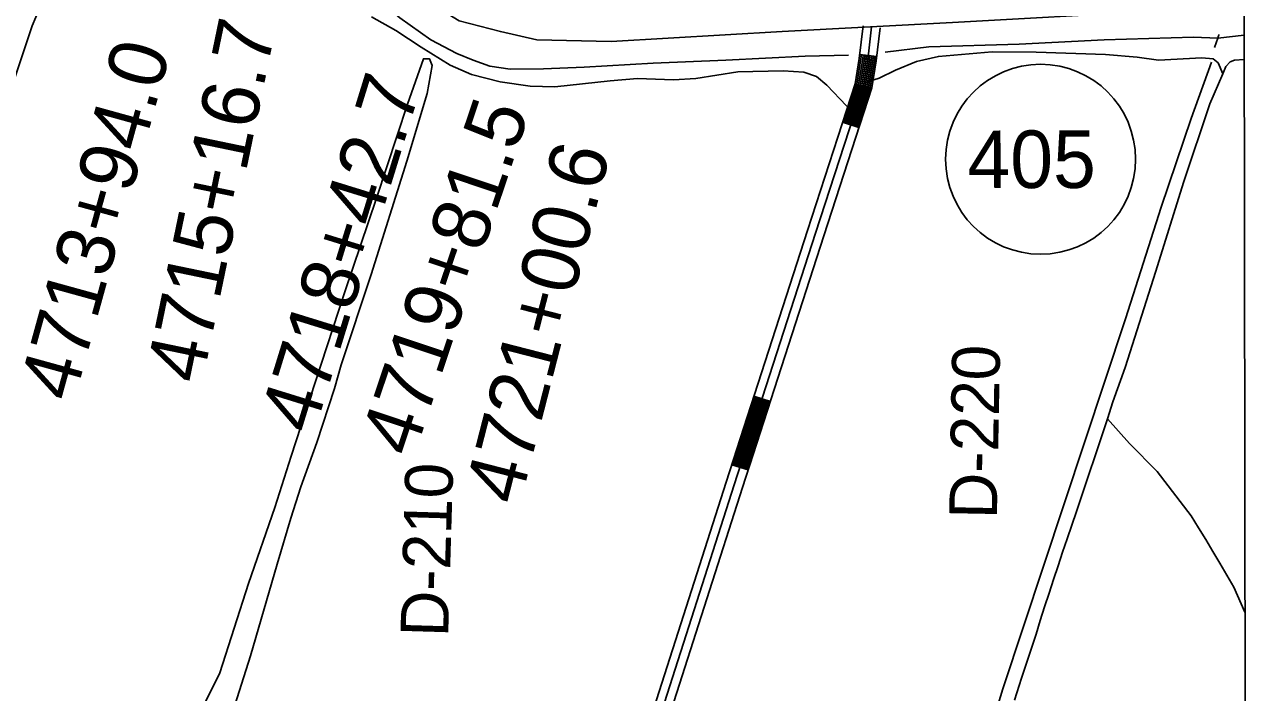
# Model space of a CAD drawing. Extents: x 3297772 to 3335630, y 634068 to 659439.
# Drawn here: x 3331326 to 3333452, y 643601 to 644761 of the extents above; entities that cross this region are included whole.
import ezdxf

# ---------------------------------------------------------------- set-up
doc = ezdxf.new("R2010")
doc.units = 0
for name, color, linetype in [('V-DTCH-CNTR', 7, 'Continuous'), ('V-GRID-FRAM', 7, 'Continuous'), ('V-RIVR-RANG-IDEN', 7, 'Continuous'), ('V-ROAD-CNTR', 7, 'Continuous'), ('V-ROAD-IDEN', 7, 'Continuous'), ('V-SITE-VEGE', 7, 'Continuous'), ('V-SURV-IDEN', 7, 'Continuous'), ('V-TOPO-SHOR', 7, 'Continuous')]:
    doc.layers.add(name, color=color, linetype=linetype)

msp = doc.modelspace()

# ---------------------------------------------------------------- linework, layer by layer
at = {"layer": 'V-DTCH-CNTR'}
msp.add_line((3333206.8, 644076.4), (3333153.2, 643915.1), dxfattribs=at)
for points in [[(3331358.2, 644804.5), (3331338.7, 644758.7), (3331279.3, 644581.4)], [(3332769.3, 644603.4), (3332753.8, 644619.7), (3332719.6, 644655.9), (3332701.7, 644670.7), (3332679.2, 644678.5), (3332643.4, 644680.5), (3332564.9, 644678.7), (3332491.7, 644667.5), (3332453.2, 644665.2), (3332390.6, 644667.2), (3332342.8, 644663.4), (3332247.1, 644653), (3332203.9, 644654.2), (3332152.2, 644661.7), (3332102.4, 644674.5), (3332065.1, 644690.5), (3332014.6, 644722.1), (3331970.7, 644750.5), (3331928.3, 644774.7)], [(3333407.2, 644675.6), (3333399.1, 644694.6), (3333390.5, 644701.6), (3333371.1, 644703.2), (3333295.6, 644699.4), (3333258.3, 644704.5), (3333203.4, 644709.2), (3333083.3, 644713.3), (3333006.7, 644713.8), (3332913.3, 644705.7), (3332875.2, 644696.8), (3332838.6, 644682.1), (3332810.2, 644668.1), (3332784, 644660.1)], [(3333444.4, 644700.4), (3333427.5, 644699.2), (3333420.1, 644696.1), (3333412.7, 644688.4), (3333407.2, 644675.6)], [(3333407.2, 644675.6), (3333384.7, 644623.5), (3333339, 644487), (3333291, 644332.6), (3333237.9, 644165.1), (3333216.4, 644105.6), (3333206.8, 644076.4)], [(3333206.8, 644076.4), (3333245.2, 644033.6), (3333293, 643984.9), (3333352.4, 643907.5)], [(3333153.2, 643915.1), (3333145, 643891.6), (3333137, 643868), (3333129, 643844.4), (3333121.1, 643820.7), (3333113.2, 643797.1), (3333105.5, 643773.4), (3333097.8, 643749.6), (3333090.3, 643725.9), (3333082.8, 643702.1), (3333070.1, 643663.9), (3333057.6, 643625.6), (3333045.3, 643587.3)], [(3333352.4, 643907.5), (3333365, 643887), (3333377.6, 643866.5), (3333389.9, 643845.9), (3333402.2, 643825.3), (3333414.2, 643804.5), (3333426.2, 643783.7), (3333445.8, 643740.2)]]:
    msp.add_lwpolyline(points, dxfattribs=at)
at = {"layer": 'V-GRID-FRAM'}
msp.add_lwpolyline([(3301870.2, 657630.6), (3333425.5, 657662.7), (3333452, 639478.7), (3301880.8, 639446.5), (3301870.2, 657630.6)], dxfattribs=at)
at = {"layer": 'V-ROAD-CNTR'}
for p, q in [((3332806.3, 644705.8), (3332776.5, 644709.2)), ((3332775.3, 644582), (3332746.7, 644591.3)), ((3332621.3, 644106.3), (3332592.8, 644115.6)), ((3332582.9, 643987.4), (3332554.3, 643996.6))]:
    msp.add_line(p, q, dxfattribs=at)
for points in [[(3331179.9, 644989.5), (3331441, 645002.9), (3331521.1, 645001.9), (3331578.7, 644990.8), (3331648, 644970.9), (3331747.7, 644939.4), (3331871.6, 644891.7), (3331950.6, 644848.9), (3332022.3, 644803.4), (3332081, 644767.4), (3332152.5, 644748.8), (3332215.7, 644734.7), (3332344.8, 644731.4), (3332641.7, 644748.8), (3332937.5, 644764.7), (3333291.4, 644784.2), (3333441.9, 644790.5)], [(3332782.3, 644758.9), (3332775.7, 644702.1), (3332768.5, 644658.2), (3332685.7, 644403.2), (3332544.4, 643966), (3332358.5, 643385.7)], [(3332797.2, 644757.1), (3332790.6, 644700), (3332783.1, 644654.7), (3332700, 644398.6), (3332558.7, 643961.4), (3332372.7, 643381.1)], [(3332812.1, 644755.4), (3332805.4, 644697.9), (3332797.7, 644651.1), (3332714.2, 644394), (3332573, 643956.8), (3332387, 643376.5)], [(3332779.5, 644708.9), (3332778.7, 644701.7), (3332771.4, 644657.5), (3332749.6, 644590.3)], [(3332782.5, 644708.5), (3332781.7, 644701.3), (3332774.3, 644656.8), (3332752.4, 644589.4)], [(3332785.5, 644708.2), (3332784.6, 644700.8), (3332777.2, 644656.1), (3332755.3, 644588.5)], [(3332788.5, 644707.8), (3332787.6, 644700.4), (3332780.2, 644655.4), (3332758.2, 644587.6)], [(3332791.4, 644707.5), (3332790.6, 644700), (3332783.1, 644654.7), (3332761, 644586.6)], [(3332794.4, 644707.1), (3332793.6, 644699.6), (3332786, 644654), (3332763.9, 644585.7)], [(3332797.4, 644706.8), (3332796.5, 644699.2), (3332788.9, 644653.2), (3332766.7, 644584.8)], [(3332800.4, 644706.4), (3332799.5, 644698.8), (3332791.9, 644652.5), (3332769.6, 644583.9)], [(3332803.4, 644706.1), (3332802.5, 644698.3), (3332794.8, 644651.8), (3332772.4, 644582.9)], [(3332595.6, 644114.6), (3332557.2, 643995.7)], [(3332598.5, 644113.7), (3332560, 643994.8)], [(3332601.3, 644112.8), (3332562.9, 643993.8)], [(3332604.2, 644111.9), (3332565.7, 643992.9)], [(3332607, 644110.9), (3332568.6, 643992)], [(3332609.9, 644110), (3332571.4, 643991.1)], [(3332612.7, 644109.1), (3332574.3, 643990.1)], [(3332615.6, 644108.2), (3332577.2, 643989.2)], [(3332618.4, 644107.2), (3332580, 643988.3)]]:
    msp.add_lwpolyline(points, dxfattribs=at)
at = {"layer": 'V-ROAD-IDEN'}
msp.add_circle((3333090.8, 644527.1), 165, dxfattribs=at)
at = {"layer": 'V-SITE-VEGE'}
for points in [[(3331639.6, 643583.3), (3331665.2, 643635), (3331714.6, 643790.3), (3331760.5, 643922.2), (3331788.6, 644011.2), (3331830.8, 644139.1), (3331881.9, 644296.6), (3331936.9, 644459.8), (3331990.8, 644622.7), (3332018.5, 644701.7), (3332027.4, 644701.6), (3332029.4, 644701.3), (3332034, 644690), (3332025.4, 644641.4), (3331989.9, 644523.9), (3331927.8, 644326.8), (3331875.9, 644170.2), (3331864.2, 644129), (3331833.4, 644035.3), (3331805.7, 643958.3), (3331788.1, 643903.5)], [(3331788.1, 643903.5), (3331764.5, 643823.5), (3331718.1, 643664.4), (3331671.1, 643516.7), (3331507.5, 643036.5), (3331490.7, 642974.7), (3331482.3, 642944.3), (3331468.1, 642899.3), (3331459.7, 642868.9), (3331446.7, 642829.6), (3331441.8, 642805.9), (3331431.1, 642771), (3331422.8, 642745.2), (3331409.7, 642703.6), (3331397.9, 642672.1), (3331381.4, 642626), (3331367.3, 642592.3), (3331351, 642560.9), (3331337, 642530.7), (3331318.3, 642488)]]:
    msp.add_lwpolyline(points, dxfattribs=at)
at = {"layer": 'V-TOPO-SHOR'}
for p, q in [((3333398.7, 644737.7), (3333393, 644721.1)), ((3333025.1, 643607.5), (3333238.1, 644249.9))]:
    msp.add_line(p, q, dxfattribs=at)
for points in [[(3331441.1, 644968.8), (3331521.6, 644969.4), (3331559.7, 644965.1), (3331643.3, 644941.3), (3331752.1, 644900.7), (3331879.6, 644848.5), (3331896.7, 644837.2), (3331930.1, 644813.8), (3331977.9, 644772.9), (3332031.5, 644734.7), (3332076.6, 644710.9), (3332105, 644699.2), (3332134.2, 644689.1), (3332169.6, 644683.6), (3332227.1, 644684.3), (3332297.9, 644687.3), (3332417.7, 644694.2), (3332544.1, 644699.1), (3332681.8, 644706), (3332756.8, 644707.8)], [(3332820.6, 644713.2), (3332896.5, 644722.4), (3333053.6, 644727.3), (3333201, 644734.5), (3333356.2, 644739), (3333398.7, 644737.7)], [(3333400.9, 644743.6), (3333400.1, 644741.7), (3333398.7, 644737.7)], [(3333444.3, 644742.6), (3333398.7, 644737.7)], [(3333387.9, 644695.8), (3333352.1, 644597.9), (3333300.1, 644443.9), (3333238.1, 644249.9)], [(3333025.1, 643607.5), (3332931.2, 643299.2), (3332902.3, 643203.4)]]:
    msp.add_lwpolyline(points, dxfattribs=at)

# ---------------------------------------------------------------- texts
at = {"layer": 'V-RIVR-RANG-IDEN'}
for s, rotation, p in [('D-220', 88.9052, (3333014.8, 643901.7)), ('D-210', 88.2922, (3332061.5, 643696.4))]:
    msp.add_text(s, height=83, rotation=rotation, dxfattribs=at).set_placement(p)
at = {"layer": 'V-ROAD-IDEN'}
msp.add_text('405', height=100, rotation=0.0735, dxfattribs=at).set_placement((3332963.7, 644477))
at = {"layer": 'V-SURV-IDEN'}
for s, rotation, p in [('4715+16.7', 78.2995, (3331633.8, 644135)), ('4713+94.0', 74.5737, (3331411, 644103)), ('4718+42.7', 72.8186, (3331827.6, 644046.8)), ('4719+81.5', 71.4463, (3332001.1, 644006.7)), ('4721+00.6', 75.5953, (3332185.7, 643924))]:
    msp.add_text(s, height=100, rotation=rotation, dxfattribs=at).set_placement(p)

doc.saveas('drawing.dxf')
